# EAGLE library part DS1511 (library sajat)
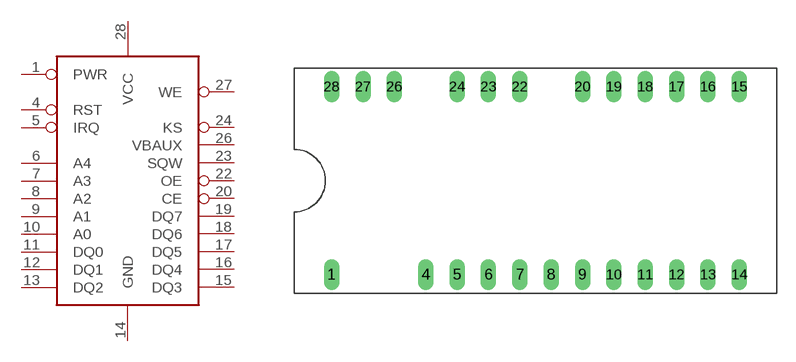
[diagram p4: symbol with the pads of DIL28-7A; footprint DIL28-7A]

Designator prefix -

## DS1511  [DIL28-7A]
1  PWR
4  RST
5  IRQ
6  A4
7  A3
8  A2
9  A1
10  A0
11  DQ0
12  DQ1
13  DQ2
14  GND
15  DQ3
16  DQ4
17  DQ5
18  DQ6
19  DQ7
20  CE
22  OE
23  SQW
24  KS
26  VBAUX
27  WE
28  VCC

## Footprint DIL28-7A (pad centres in mm)
drill 0.3 pad 1.27 long: 1 -16.51,-7.62; 4 -8.89,-7.62; 5 -6.35,-7.62; 6 -3.81,-7.62; 7 -1.27,-7.62; 8 1.27,-7.62; 9 3.81,-7.62; 10 6.35,-7.62; 11 8.89,-7.62; 12 11.43,-7.62; 13 13.97,-7.62; 14 16.51,-7.62; 15 16.51,7.62; 16 13.97,7.62; 17 11.43,7.62; 18 8.89,7.62; 19 6.35,7.62; 20 3.81,7.62; 22 -1.27,7.62; 23 -3.81,7.62; 24 -6.35,7.62; 26 -11.43,7.62; 27 -13.97,7.62; 28 -16.51,7.62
